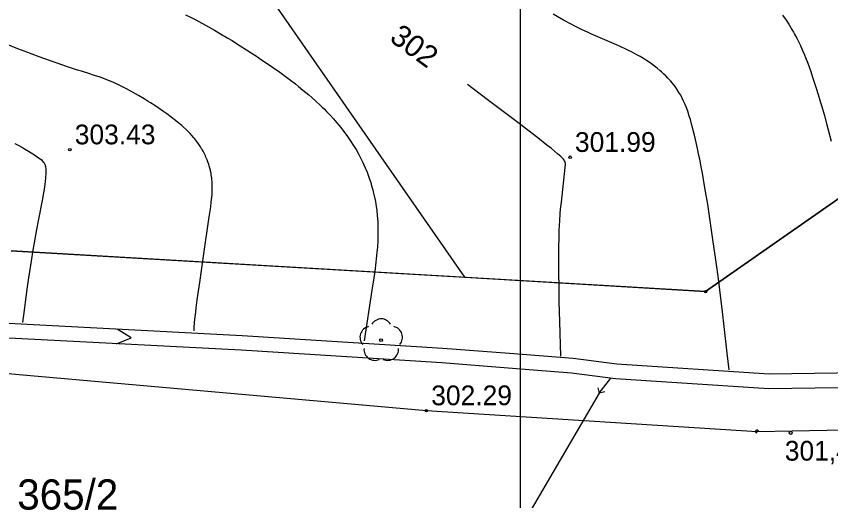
# Model space of a CAD drawing. Extents: x 7477803 to 7478145, y 5500698 to 5500984.
# Drawn here: x 7477982.63 to 7478010.69, y 5500809.46 to 5500826.14 of the extents above; entities that cross this region are included whole.
import ezdxf

# ---------------------------------------------------------------- set-up
doc = ezdxf.new("R2010")
doc.units = 0
for name, color, linetype in [('203-Punkt załamania granicy działki nie stabilizowany', 7, 'Continuous'), ('gr_dzialki', 7, 'Continuous'), ('gr_klasy', 7, 'Continuous'), ('jezdnia', 7, 'Continuous'), ('nr_dzialki', 7, 'Continuous'), ('pkt_wys', 7, 'Continuous'), ('przepust', 7, 'Continuous'), ('robocza49', 7, 'Continuous'), ('rowy', 7, 'Continuous'), ('uwagi_projektanci', 7, 'Continuous'), ('warst_ciagla', 7, 'Continuous'), ('warst_opis', 7, 'Continuous'), ('warst_przeryw', 7, 'Continuous')]:
    doc.layers.add(name, color=color, linetype=linetype)

# ---------------------------------------------------------------- blocks, each defined once
blk = doc.blocks.new('203')
blk.add_circle((0, 0), 0.045)
blk = doc.blocks.new('801_1')
at = {"layer": 'pkt_wys'}
blk.add_circle((0, 0), 0.045, dxfattribs=at)
blk.add_circle((0, 0), 0.045, dxfattribs=at)
blk = doc.blocks.new('801')
at = {"layer": 'pkt_wys'}
blk.add_circle((0, 0), 0.045, dxfattribs=at)
blk.add_circle((0, 0), 0.045, dxfattribs=at)
blk = doc.blocks.new('413_5')
at = {"layer": 'przepust'}
for p in [(-0.35, 0.35), (-0.35, -0.35)]:
    blk.add_line(p, (0, 0), dxfattribs=at)
blk = doc.blocks.new('801_5_3')
at = {"layer": 'pkt_wys'}
blk.add_circle((0, 0), 0.05, dxfattribs=at)
blk.add_circle((0, 0), 0.05, dxfattribs=at)
blk = doc.blocks.new('922_5_1')
at = {"layer": 'uwagi_projektanci'}
blk.add_circle((-0.001, 0), 0.05, dxfattribs=at)
blk.add_circle((-0.001, 0), 0.05, dxfattribs=at)
for centre, start, end in [((0.004, 0.357), 30.1243, 149.8757), ((-0.353, 0.098), 101.9988, 221.9759), ((0.362, 0.098), 318.0241, 78.0012), ((-0.215, -0.321), 174.335, 293.7607), ((0.225, -0.321), 246.2393, 5.665)]:
    blk.add_arc(centre, 0.375, start, end, dxfattribs=at)

msp = doc.modelspace()

# ---------------------------------------------------------------- linework, layer by layer
at = {"layer": 'gr_dzialki'}
for points in [[(7478024.7, 5500829.46), (7478006.38, 5500816.66)], [(7478006.38, 5500816.66), (7477982.46, 5500818.07)]]:
    msp.add_lwpolyline(points, dxfattribs=at)
at = {"layer": 'gr_klasy'}
for points in [[(7477998.08, 5500817.16), (7477980.49, 5500842.45)], [(7478006.38, 5500816.66), (7478024.7, 5500829.46)], [(7477982.46, 5500818.07), (7477998.08, 5500817.16)], [(7477998.08, 5500817.16), (7478006.38, 5500816.66)]]:
    msp.add_lwpolyline(points, dxfattribs=at)
at = {"layer": 'jezdnia'}
for points in [[(7478008.149, 5500811.845), (7478011.769, 5500811.909), (7478014.098, 5500812.451), (7478017.047, 5500813.895), (7478021.153, 5500817.039), (7478024.239, 5500820.732), (7478026.136, 5500823.914), (7478027.522, 5500827.266), (7478028.159, 5500830.207), (7478028.284, 5500834.367), (7478027.822, 5500836.806), (7478026.257, 5500841.255), (7478025.204, 5500843.403), (7478022.901, 5500846.211), (7478018.407, 5500849.956), (7478013.603, 5500853.721), (7478010.61, 5500855.711)], [(7477875.926, 5500787.879), (7477876.814, 5500788.851), (7477888.353, 5500798.574), (7477893.52, 5500801.94), (7477899.965, 5500805.717), (7477906.333, 5500808.394), (7477918.837, 5500813.137), (7477925.266, 5500814.534), (7477933.655, 5500815.503), (7477941.064, 5500815.881), (7477951.515, 5500815.693), (7477966.065, 5500814.879), (7477981.427, 5500813.916), (7477996.758, 5500812.562), (7478008.149, 5500811.845)]]:
    msp.add_lwpolyline(points, dxfattribs=at)
at = {"layer": 'pkt_wys'}
msp.add_lwpolyline([(7478008.146, 5500811.795), (7478008.149, 5500811.845), (7478008.197, 5500811.858)], dxfattribs=at)
msp.add_lwpolyline([(7478008.146, 5500811.795), (7478008.149, 5500811.845), (7478008.197, 5500811.858)], dxfattribs=at)
msp.add_arc((7478008.149, 5500811.845), 0.05, 15.4119, 267.2002, dxfattribs=at)
msp.add_arc((7478008.149, 5500811.845), 0.05, 15.4119, 267.2002, dxfattribs=at)
at = {"layer": 'przepust'}
msp.add_line((7478002.71, 5500813.159), (7477997.502, 5500804.278), dxfattribs=at)
at = {"layer": 'robocza49'}
msp.add_line((7478000, 5500750), (7478000, 5500973.047), dxfattribs=at)
at = {"layer": 'rowy'}
msp.add_line((7478002.71, 5500813.159), (7478003.118, 5500813.679), dxfattribs=at)
for points in [[(7478022.21, 5500842.975), (7478023.266, 5500841.06), (7478024.262, 5500838.724), (7478025.045, 5500836.559), (7478025.636, 5500834.458), (7478026.16, 5500832.468), (7478026.117, 5500829.33), (7478025.782, 5500826.86), (7478023.298, 5500822.081), (7478021.376, 5500819.51), (7478017.996, 5500816.414), (7478015.397, 5500814.781), (7478012.422, 5500813.577), (7478010.943, 5500813.35), (7478008.556, 5500813.315), (7478003.273, 5500813.659), (7478001.759, 5500813.856), (7477999.58, 5500814.028), (7477997.292, 5500814.207), (7477990.382, 5500814.641), (7477980.361, 5500815.165)], [(7478021.784, 5500842.711), (7478022.816, 5500840.841), (7478023.796, 5500838.541), (7478024.569, 5500836.406), (7478025.154, 5500834.326), (7478025.659, 5500832.406), (7478025.618, 5500829.368), (7478025.298, 5500827.014), (7478022.873, 5500822.348), (7478021.004, 5500819.847), (7478017.692, 5500816.813), (7478015.168, 5500815.228), (7478012.289, 5500814.063), (7478010.902, 5500813.85), (7478008.569, 5500813.815), (7478003.321, 5500814.157), (7478001.811, 5500814.354), (7477999.619, 5500814.526), (7477997.327, 5500814.706), (7477990.411, 5500815.14), (7477980.39, 5500815.664)], [(7477986.083, 5500814.866), (7477986.594, 5500815.072), (7477986.109, 5500815.365)]]:
    msp.add_lwpolyline(points, dxfattribs=at)
at = {"layer": 'warst_ciagla'}
for points in [[(7478009.03, 5500826.182), (7478009.154, 5500826.006), (7478009.243, 5500825.873), (7478009.354, 5500825.692), (7478009.407, 5500825.6), (7478009.445, 5500825.531), (7478009.519, 5500825.391), (7478009.59, 5500825.25), (7478009.635, 5500825.156), (7478009.72, 5500824.965), (7478009.781, 5500824.821), (7478009.82, 5500824.725), (7478009.895, 5500824.532), (7478009.999, 5500824.241), (7478010.064, 5500824.049), (7478010.187, 5500823.666), (7478010.252, 5500823.453), (7478010.337, 5500823.174), (7478010.378, 5500823.036), (7478010.457, 5500822.763), (7478010.557, 5500822.405), (7478010.604, 5500822.229), (7478010.705, 5500821.84)], [(7477988.755, 5500815.311), (7477988.765, 5500815.451), (7477988.787, 5500815.711), (7477988.813, 5500815.949), (7477988.831, 5500816.098), (7477988.868, 5500816.374), (7477988.951, 5500816.971), (7477989.091, 5500817.958), (7477989.278, 5500819.234), (7477989.329, 5500819.58), (7477989.351, 5500819.747), (7477989.368, 5500819.912), (7477989.375, 5500819.993), (7477989.384, 5500820.153), (7477989.385, 5500820.232), (7477989.384, 5500820.349), (7477989.378, 5500820.465), (7477989.373, 5500820.516), (7477989.366, 5500820.584), (7477989.361, 5500820.617), (7477989.35, 5500820.693), (7477989.341, 5500820.742), (7477989.327, 5500820.808), (7477989.32, 5500820.841), (7477989.304, 5500820.907), (7477989.28, 5500820.993), (7477989.266, 5500821.036), (7477989.233, 5500821.132), (7477989.206, 5500821.203), (7477989.166, 5500821.297), (7477989.145, 5500821.343), (7477989.093, 5500821.447), (7477989.068, 5500821.493), (7477989.034, 5500821.553), (7477989.016, 5500821.583), (7477988.974, 5500821.651), (7477988.883, 5500821.783), (7477988.84, 5500821.841), (7477988.78, 5500821.918), (7477988.749, 5500821.956), (7477988.675, 5500822.041), (7477988.618, 5500822.104), (7477988.537, 5500822.188), (7477988.496, 5500822.229), (7477988.398, 5500822.32), (7477988.331, 5500822.381), (7477988.191, 5500822.499), (7477988.119, 5500822.557), (7477987.972, 5500822.671), (7477987.821, 5500822.782), (7477987.72, 5500822.854), (7477987.517, 5500822.993), (7477987.404, 5500823.068), (7477987.254, 5500823.165), (7477987.18, 5500823.212), (7477987.033, 5500823.303), (7477986.839, 5500823.418), (7477986.743, 5500823.472), (7477986.53, 5500823.59), (7477986.425, 5500823.645), (7477986.287, 5500823.715), (7477986.218, 5500823.749), (7477986.082, 5500823.813), (7477985.902, 5500823.892), (7477985.814, 5500823.93), (7477985.617, 5500824.007), (7477985.52, 5500824.042), (7477985.328, 5500824.108), (7477985.136, 5500824.169), (7477984.876, 5500824.248), (7477984.743, 5500824.289), (7477984.435, 5500824.388), (7477984.002, 5500824.535), (7477983.776, 5500824.615), (7477983.426, 5500824.742), (7477982.937, 5500824.928), (7477982.683, 5500825.027), (7477982.143, 5500825.244)], [(7478001.39, 5500814.434), (7478001.353, 5500815.631), (7478001.337, 5500816.312), (7478001.329, 5500816.719), (7478001.321, 5500817.427), (7478001.321, 5500817.875), (7478001.323, 5500818.138), (7478001.331, 5500818.586), (7478001.337, 5500818.776), (7478001.352, 5500819.098), (7478001.37, 5500819.356), (7478001.383, 5500819.501), (7478001.409, 5500819.747), (7478001.542, 5500820.939), (7478001.551, 5500821.035), (7478001.55, 5500821.075), (7478001.543, 5500821.112), (7478001.537, 5500821.13), (7478001.518, 5500821.167), (7478001.505, 5500821.187), (7478001.481, 5500821.217), (7478001.432, 5500821.27), (7478001.39, 5500821.31), (7478001.28, 5500821.407), (7478001.064, 5500821.587), (7478000.911, 5500821.71), (7478000.602, 5500821.952), (7477999.908, 5500822.484), (7477998.858, 5500823.276), (7477998.172, 5500823.791)]]:
    msp.add_lwpolyline(points, dxfattribs=at)
at = {"layer": 'warst_przeryw'}
for points in [[(7478007.188, 5500813.967), (7478007.187, 5500813.972), (7478007.126, 5500814.547), (7478007.021, 5500815.455), (7478006.959, 5500815.969), (7478006.817, 5500817.096), (7478006.74, 5500817.681), (7478006.621, 5500818.541), (7478006.502, 5500819.343), (7478006.449, 5500819.678), (7478006.379, 5500820.104), (7478006.344, 5500820.308), (7478006.266, 5500820.746), (7478006.227, 5500820.954), (7478006.176, 5500821.22), (7478006.15, 5500821.347), (7478006.099, 5500821.593), (7478006.03, 5500821.9), (7478005.996, 5500822.044), (7478005.92, 5500822.348), (7478005.852, 5500822.594), (7478005.817, 5500822.709), (7478005.763, 5500822.873), (7478005.705, 5500823.029), (7478005.675, 5500823.103), (7478005.609, 5500823.248), (7478005.575, 5500823.319), (7478005.519, 5500823.422), (7478005.459, 5500823.524), (7478005.371, 5500823.656), (7478005.325, 5500823.721), (7478005.225, 5500823.848), (7478005.179, 5500823.904), (7478005.114, 5500823.977), (7478005.08, 5500824.013), (7478005.003, 5500824.093), (7478004.942, 5500824.152), (7478004.858, 5500824.229), (7478004.815, 5500824.267), (7478004.714, 5500824.352), (7478004.572, 5500824.461), (7478004.499, 5500824.515), (7478004.345, 5500824.619), (7478004.274, 5500824.665), (7478004.178, 5500824.724), (7478004.128, 5500824.753), (7478004.014, 5500824.818), (7478003.926, 5500824.866), (7478003.806, 5500824.928), (7478003.745, 5500824.959), (7478003.603, 5500825.026), (7478003.307, 5500825.159), (7478002.66, 5500825.437), (7478002.428, 5500825.54), (7478002.309, 5500825.595), (7478002.127, 5500825.682), (7478001.877, 5500825.807), (7478001.749, 5500825.873), (7478001.487, 5500826.012), (7478001.124, 5500826.212)], [(7477988.464, 5500826.196), (7477988.614, 5500826.12), (7477988.816, 5500826.016), (7477988.917, 5500825.962), (7477989.146, 5500825.838), (7477989.455, 5500825.665), (7477989.61, 5500825.575), (7477989.924, 5500825.389), (7477990.065, 5500825.304), (7477990.253, 5500825.188), (7477990.348, 5500825.128), (7477990.562, 5500824.992), (7477990.724, 5500824.888), (7477990.941, 5500824.745), (7477991.05, 5500824.672), (7477991.342, 5500824.473), (7477991.489, 5500824.371), (7477991.708, 5500824.216), (7477992.034, 5500823.976), (7477992.247, 5500823.813), (7477992.353, 5500823.73), (7477992.508, 5500823.604), (7477992.712, 5500823.434), (7477992.811, 5500823.347), (7477992.957, 5500823.217), (7477993.098, 5500823.085), (7477993.167, 5500823.019), (7477993.235, 5500822.952), (7477993.323, 5500822.863), (7477993.367, 5500822.818), (7477993.452, 5500822.728), (7477993.563, 5500822.606), (7477993.616, 5500822.545), (7477993.734, 5500822.407), (7477993.809, 5500822.314), (7477993.907, 5500822.189), (7477993.954, 5500822.127), (7477994.046, 5500822), (7477994.162, 5500821.83), (7477994.217, 5500821.745), (7477994.336, 5500821.55), (7477994.419, 5500821.403), (7477994.523, 5500821.205), (7477994.571, 5500821.104), (7477994.606, 5500821.029), (7477994.651, 5500820.928), (7477994.672, 5500820.877), (7477994.714, 5500820.775), (7477994.766, 5500820.638), (7477994.79, 5500820.569), (7477994.842, 5500820.414), (7477994.874, 5500820.309), (7477994.913, 5500820.169), (7477994.931, 5500820.098), (7477994.964, 5500819.956), (7477995.002, 5500819.766), (7477995.019, 5500819.67), (7477995.05, 5500819.452), (7477995.068, 5500819.287), (7477995.084, 5500819.065), (7477995.088, 5500818.953), (7477995.09, 5500818.869), (7477995.091, 5500818.7), (7477995.088, 5500818.53), (7477995.083, 5500818.416), (7477995.07, 5500818.189), (7477995.056, 5500818.019), (7477995.045, 5500817.906), (7477995.02, 5500817.681), (7477994.978, 5500817.349), (7477994.947, 5500817.131), (7477994.883, 5500816.711), (7477994.616, 5500814.971)], [(7477982.584, 5500821.764), (7477982.702, 5500821.7), (7477982.848, 5500821.619), (7477982.916, 5500821.581), (7477983.056, 5500821.499), (7477983.15, 5500821.442), (7477983.26, 5500821.372), (7477983.308, 5500821.34), (7477983.402, 5500821.272), (7477983.454, 5500821.232), (7477983.484, 5500821.206), (7477983.534, 5500821.158), (7477983.563, 5500821.125), (7477983.58, 5500821.104), (7477983.606, 5500821.064), (7477983.615, 5500821.045), (7477983.63, 5500821.008), (7477983.639, 5500820.973), (7477983.642, 5500820.949), (7477983.646, 5500820.9), (7477983.648, 5500820.767), (7477983.646, 5500820.703), (7477983.641, 5500820.612), (7477983.638, 5500820.565), (7477983.627, 5500820.453), (7477983.605, 5500820.271), (7477983.593, 5500820.185), (7477983.574, 5500820.066), (7477983.563, 5500820.004), (7477983.537, 5500819.86), (7477983.383, 5500819.101), (7477983.325, 5500818.796), (7477983.245, 5500818.343), (7477983.204, 5500818.098), (7477983.141, 5500817.705), (7477983.055, 5500817.135), (7477983.011, 5500816.831), (7477982.937, 5500816.299), (7477982.9, 5500816.022), (7477982.847, 5500815.594)]]:
    msp.add_lwpolyline(points, dxfattribs=at)

# ---------------------------------------------------------------- block references
at = {"layer": '203-Punkt załamania granicy działki nie stabilizowany'}
msp.add_blockref('203', (7478006.38, 5500816.66), dxfattribs=at)
at = {"layer": 'pkt_wys', "rotation": 0.0626175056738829}
for name, p in [('801_1', (7477984.478, 5500821.549)), ('801_1', (7478001.709, 5500821.288)), ('801', (7477996.758, 5500812.562)), ('801_5_3', (7478009.309, 5500811.796))]:
    msp.add_blockref(name, p, dxfattribs=at)
at = {"layer": 'przepust', "xscale": 0.4000000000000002, "yscale": 0.4000000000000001, "rotation": -120.38633992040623}
msp.add_blockref('413_5', (7478002.71, 5500813.159), dxfattribs=at)
at = {"layer": 'uwagi_projektanci'}
msp.add_blockref('922_5_1', (7477995.2, 5500814.99), dxfattribs=at)

# ---------------------------------------------------------------- texts
at = {"layer": 'nr_dzialki'}
msp.add_text('365/2', height=1.04, dxfattribs=at).set_placement((7477982.666, 5500809.155))
at = {"layer": 'pkt_wys'}
for s, p in [('303.43', (7477984.647, 5500821.733)), ('301.99', (7478001.877, 5500821.472)), ('302.29', (7477996.927, 5500812.747)), ('301,47', (7478009.106, 5500810.84))]:
    msp.add_text(s, height=0.68, rotation=0.0626, dxfattribs=at).set_placement(p)
at = {"layer": 'warst_opis'}
msp.add_text('302', height=0.75, rotation=323.7784, dxfattribs=at).set_placement((7477995.454, 5500825.318))

doc.saveas('drawing.dxf')
